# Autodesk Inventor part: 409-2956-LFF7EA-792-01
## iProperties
Shininess: 64.0
Angle Display Precision: 2
Document Length Units: 11272
Document Angle Units: 11279
Document Time Units: 11290
Document Mass Units: 11286
Document Length Units Precision: 3
Document Angle Units Precision: 2
Compacted: True
Created: 2002-04
Part Number: 409-2956-LFF7EA-792-01
Description: DISCHARGE PIPE STAND ANGLE
Document SubType Name: Modeling
Designer: S. Boerckel
Mass: 4272.04 g
Surface Area: 1782.52 cm^2
Volume: 544.209 cm^3
Density: 7.85 g/cm^3
Cost Center: 2 x 2 x 1/4 ANGLE
Material: ASTM A36
Engineer: S. Boerckel
User Status: SAW
Density: 0.0
Volumn: 0.0
Area: 0.0
PropertySet Name: Model Information
Control State: 0
Master: False
Checked Out: False
length: 35.503 in
SMR: =<COST CENTER> - <MATERIAL>
Author: S. Boerckel
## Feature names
1. Extrusion1
